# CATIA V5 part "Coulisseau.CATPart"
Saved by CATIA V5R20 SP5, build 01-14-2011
Part number: Coulisseau1
Bounding box of the stored display mesh (mm): x -60 to -40, y -3.5 to 3.5, z -20 to 12
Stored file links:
  F:\nsarlin\Coulisseau.CATPart
  J:\IAO\Mecanisme_a_bielle_et_deux_coulisseaux.CATProduct
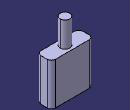
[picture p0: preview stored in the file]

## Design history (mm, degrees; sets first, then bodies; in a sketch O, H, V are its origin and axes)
External parameters (linked from other documents)
  External.Largeur = 7 mm
  External.Longueur_couli = 20 mm
  External.Epaisseur = 20 mm
  External.Longueur_Axe = 8 mm
Set1
  Plane1 "Plan_de_ref": linked copy from another document
  Point1 "Point_coulisseau1": linked copy from another document
Body1 (main body)
  Sketch1 on Plane1, origin (-50, 0, 0), H (1, 0, 0), V (0, 1, 0)
    line L1 (-8, 3.5) -> (8, 3.5)
    arc A1 centre (8, 1.5) radius 2 from (8, 3.5) to (10, 1.5) cw
    line L2 (10, 1.5) -> (10, -1.5)
    arc A2 centre (8, -1.5) radius 2 from (10, -1.5) to (8, -3.5) cw
    line L3 (8, -3.5) -> (-8, -3.5)
    arc A3 centre (-8, -1.5) radius 2 from (-8, -3.5) to (-10, -1.5) cw
    line L4 (-10, -1.5) -> (-10, 1.5)
    arc A4 centre (-8, 1.5) radius 2 from (-10, 1.5) to (-8, 3.5) cw
    distance L1 L3 = 7 {= External.Largeur}
    radius A1 = 2
    radius A2 = 2
    radius A4 = 2
    radius A3 = 2
    distance L3 H = 3.5 {= External.Largeur /2}
    distance L4 V = 10 {= External.Longueur_couli /2}
    distance L2 L4 = 20 {= External.Longueur_couli}
    horizontal: L1 H
    tangency: A1 L1, L2 A1, A2 L2, L3 A2, A3 L3, L4 A3, A4 L4, A4 L1
  Pad1 "Partie_coulissante": profile Sketch1, direction (0, 0, -1), length 20 {= External.Epaisseur}
  Sketch2 on start face of Pad1, origin (-50, 0, 0), H (1, 0, 0), V (0, 1, 0)
    circle A1 centre (0, 0) radius 2.3333
    point P1 (0, 0)
    reference projected point E1 (0, 0) from Point1
    radius A1 = 2.3333 {= External.Largeur /3}
    coincidence: P1 E1
  Pad2 "Partie_pivotante": profile Sketch2, direction (0, 0, 1), length 12 {= External.Epaisseur/2 +2mm}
